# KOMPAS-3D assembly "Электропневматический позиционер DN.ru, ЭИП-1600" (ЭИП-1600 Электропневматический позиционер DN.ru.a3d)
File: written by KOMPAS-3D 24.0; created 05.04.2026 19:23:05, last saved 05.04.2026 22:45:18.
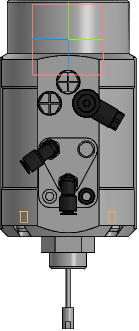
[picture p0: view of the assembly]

Document properties: Автор: R2D2; Полное имя файла: C:\Users\R2D2\Desktop\ЭИП-1600 Электропневматический позиционер DN.ru — копия\5-25\исходные материалы\ЭИП-1600 Электропневматический позиционер DN.ru.a3d

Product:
- Component [detail]: корпус  | qty 1  | pos. 1  | Масса: 9.19942; Раздел спецификации: Прочие изделия; Примечание: D900-02741; Автор: R2D2; source file: Корпус.m3d
- Component [detail]: Тело 13  | qty 1  | pos. 2  | Масса: 0.071175; source file: Г клема.m3d
- Component [detail]: Клема  | qty 1  | pos. 3  | Масса: 0.013339; source file: Клема.m3d
- Component [detail]: Тело 12  | qty 1  | pos. 4  | Масса: 0.022159; source file: Пневматический разъем.m3d
- Component [detail]: Тело 12  | qty 1  | pos. 5  | Масса: 0.022159; source file: Пневматический разъем.m3d
- Component [detail]: Тело 12  | qty 1  | pos. 6  | Масса: 0.022159; source file: Пневматический разъем.m3d
- Component [standard]: Cheese head screw ISO 7048 - М6 x 10 - H  | qty 4  | Материал: Не определено (density 0 kg/m3); Масса: 0.00392; Раздел спецификации: Стандартные изделия; Рассекать на разрезах: no
- Component [detail]: шток  | qty 1  | pos. 7  | Масса: 0.134738; source file: шток.m3d
- Part/product: Электропневматический позиционер DN.ru  | designation ЭИП-1600
    Масса: 0.14
    Раздел спецификации: Прочие изделия
    Примечание: D900-02742

Expressions: D900-02741
Referenced files in C:\Users\R2D2\Desktop\ЭИП-1600 Электропневматический позиционер DN.ru — копия\5-25\исходные материалы\: Корпус.m3d, Г клема.m3d, Клема.m3d, Пневматический разъем.m3d, шток.m3d
Referenced files in C:\Program Files\ASCON\KOMPAS-3D v24\Libs\PolynomLib\DATA\vault\Methods\Kompas\3D\: PLib_Screw_ISO_7048_1500.m3d
Referenced files in E:\Работа\Зайцев\Аксессуары для пневмоприводов\Электропневматические позиционеры DN.ru\ЭИП Электропневматический позиционер DN.ru\ЭИП-1500 Электропневматический позиционер DN.ru\5-25\: Пневматический разъем.m3d
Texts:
  Cheese head screw
  BOSimple***PART:5dfe4ae6-934c-9717-4054-6a9437cf2718***SHORTLOC:B94B_D4FD7824BC314902[H;1;10;6;-;Undefined]
  Программные изделия  и базы данных
  ЭИП-1600
  Тело 12 (1)
  Тело 12 (2)
  Тело 12 (3)
  Cheese head screw ISO 7048 - М6 x 10 - H (1)
  Cheese head screw ISO 7048 - М6 x 10 - H (2)
  Cheese head screw ISO 7048 - М6 x 10 - H (3)
  Cheese head screw ISO 7048 - М6 x 10 - H (4)
  Плоскость XY.Начало координат
  Ось Y.Начало координат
